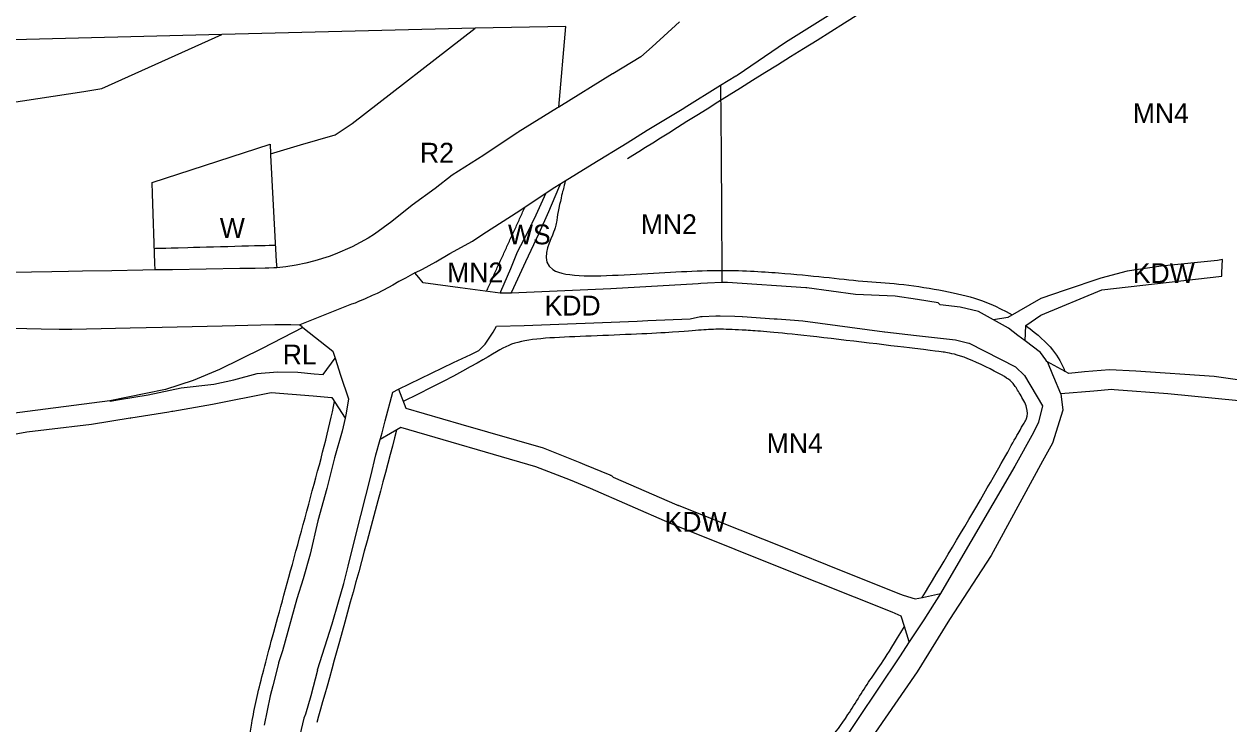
# Model space of a CAD drawing. Extents: x 7413438 to 7416393, y 5541665 to 5544118.
# Drawn here: x 7415261.6 to 7415625.7, y 5542999.4 to 5543211 of the extents above; entities that cross this region are included whole.
import ezdxf

# ---------------------------------------------------------------- set-up
doc = ezdxf.new("R2010")
doc.units = 0
for name, color, linetype in [('linie_rozgraniczajace', 7, 'Continuous'), ('linie_zabudowy_nieprzekraczalne', 7, 'Continuous'), ('oznaczenia_przeznaczen', 7, 'Continuous')]:
    doc.layers.add(name, color=color, linetype=linetype)

msp = doc.modelspace()

# ---------------------------------------------------------------- linework, layer by layer
at = {"layer": 'linie_rozgraniczajace'}
for p, q in [((7415491.71, 5543205.57), (7415509.39, 5543216.65)), ((7415397.9, 5543209.78), (7415321.33, 5543207.81)), ((7415360.73, 5543180.92), (7415397.9, 5543209.78)), ((7415425.26, 5543210.29), (7415397.9, 5543209.78)), ((7415423.19, 5543185.89), (7415425.26, 5543210.29)), ((7415459.66, 5543211.68), (7415451.33, 5543204.06)), ((7415321.33, 5543207.81), (7415254.41, 5543206.08)), ((7415285.02, 5543191.48), (7415321.33, 5543207.81)), ((7415477.03, 5543195.55), (7415491.71, 5543205.57)), ((7415451.33, 5543204.06), (7415447.97, 5543201.09)), ((7415447.97, 5543201.09), (7415439.5, 5543195.95)), ((7415439.43, 5543195.91), (7415423.19, 5543185.89)), ((7415439.5, 5543195.95), (7415439.43, 5543195.91)), ((7415472.07, 5543192.47), (7415476.65, 5543195.3)), ((7415476.65, 5543195.3), (7415476.73, 5543195.35)), ((7415476.73, 5543195.35), (7415477.03, 5543195.55)), ((7415256.5, 5543187.04), (7415279.6, 5543190.64)), ((7415279.6, 5543190.64), (7415285.02, 5543191.48)), ((7415461.04, 5543185.63), (7415472.07, 5543192.47)), ((7415472.07, 5543192.47), (7415472.21, 5543171.96)), ((7415422.79, 5543185.63), (7415410.86, 5543178.33)), ((7415423.19, 5543185.89), (7415422.79, 5543185.63)), ((7415449.91, 5543178.88), (7415460.96, 5543185.58)), ((7415460.96, 5543185.58), (7415461.04, 5543185.63)), ((7415355.58, 5543177.53), (7415360.73, 5543180.92)), ((7415345.11, 5543174.46), (7415355.58, 5543177.53)), ((7415410.54, 5543178.12), (7415400.48, 5543171.4)), ((7415410.74, 5543178.25), (7415410.54, 5543178.12)), ((7415410.86, 5543178.33), (7415410.74, 5543178.25)), ((7415443.8, 5543175.11), (7415449.91, 5543178.88)), ((7415300.24, 5543163.07), (7415335.89, 5543174.72)), ((7415335.89, 5543174.72), (7415336.05, 5543171.74)), ((7415336.05, 5543171.74), (7415345.11, 5543174.46)), ((7415433.28, 5543168.61), (7415443.8, 5543175.11)), ((7415336.05, 5543171.74), (7415336.07, 5543171.37)), ((7415336.07, 5543171.37), (7415337.79, 5543139.23)), ((7415400.48, 5543171.4), (7415390.95, 5543165.27)), ((7415472.21, 5543171.96), (7415472.33, 5543153.71)), ((7415390.95, 5543165.27), (7415385.76, 5543161.32)), ((7415423.77, 5543162.78), (7415433.25, 5543168.59)), ((7415433.25, 5543168.59), (7415433.28, 5543168.61)), ((7415300.35, 5543159.68), (7415300.24, 5543163.07)), ((7415421.48, 5543161.38), (7415423.77, 5543162.78)), ((7415423.15, 5543161.45), (7415423.77, 5543162.78)), ((7415301.08, 5543138.66), (7415300.35, 5543159.68)), ((7415385.76, 5543161.32), (7415378.88, 5543156.22)), ((7415411.51, 5543154.72), (7415419.23, 5543159.88)), ((7415419.23, 5543159.88), (7415416.2, 5543153.25)), ((7415419.23, 5543159.88), (7415421.48, 5543161.38)), ((7415420.15, 5543154.28), (7415423.15, 5543161.45)), ((7415378.88, 5543156.22), (7415372.72, 5543151.29)), ((7415400.25, 5543147.48), (7415411.36, 5543154.62)), ((7415411.36, 5543154.62), (7415411.51, 5543154.72)), ((7415417.24, 5543147.81), (7415420.15, 5543154.28)), ((7415372.72, 5543151.29), (7415367.43, 5543147.42)), ((7415416.2, 5543153.25), (7415413.74, 5543147.95)), ((7415472.33, 5543153.71), (7415472.45, 5543137)), ((7415367.43, 5543147.42), (7415365.51, 5543146.23)), ((7415397.08, 5543145.37), (7415400.25, 5543147.48)), ((7415413.74, 5543147.95), (7415410.62, 5543141.99)), ((7415413.21, 5543139.23), (7415417.24, 5543147.81)), ((7415360.69, 5543143.62), (7415355.56, 5543141.38)), ((7415365.51, 5543146.23), (7415360.69, 5543143.62)), ((7415390.25, 5543141.62), (7415397.08, 5543145.37)), ((7415353.72, 5543140.7), (7415349.44, 5543139.37)), ((7415355.56, 5543141.38), (7415353.72, 5543140.7)), ((7415386, 5543139.14), (7415390.25, 5543141.62)), ((7415410.62, 5543141.99), (7415408.59, 5543137.03)), ((7415623.74, 5543139.84), (7415622.21, 5543139.49)), ((7415623.56, 5543135.88), (7415623.74, 5543139.84)), ((7415270, 5543136.09), (7415257.64, 5543135.88)), ((7415274.96, 5543136.18), (7415270, 5543136.09)), ((7415279.27, 5543136.26), (7415274.96, 5543136.18)), ((7415288.11, 5543136.41), (7415279.27, 5543136.26)), ((7415297.42, 5543136.57), (7415288.11, 5543136.41)), ((7415301.15, 5543136.66), (7415297.42, 5543136.57)), ((7415301.15, 5543136.66), (7415301.08, 5543138.66)), ((7415306.39, 5543136.73), (7415301.15, 5543136.66)), ((7415326.8, 5543137.06), (7415306.39, 5543136.73)), ((7415331.38, 5543137.12), (7415326.8, 5543137.06)), ((7415334.46, 5543137.17), (7415331.38, 5543137.12)), ((7415335.54, 5543137.18), (7415334.46, 5543137.17)), ((7415337, 5543137.26), (7415335.54, 5543137.18)), ((7415337.92, 5543137.33), (7415337, 5543137.26)), ((7415337.79, 5543139.23), (7415337.92, 5543137.33)), ((7415340.64, 5543137.62), (7415337.92, 5543137.33)), ((7415343.84, 5543138.11), (7415340.64, 5543137.62)), ((7415346.73, 5543138.69), (7415343.84, 5543138.11)), ((7415349.44, 5543139.37), (7415346.73, 5543138.69)), ((7415379.69, 5543135.76), (7415381.97, 5543136.9)), ((7415381.97, 5543136.9), (7415386, 5543139.14)), ((7415408.59, 5543137.03), (7415405.53, 5543129.99)), ((7415409.56, 5543131.35), (7415413.21, 5543139.23)), ((7415472.45, 5543137), (7415472.47, 5543132.84)), ((7415594.94, 5543136.31), (7415586.97, 5543134.21)), ((7415605.22, 5543137.76), (7415594.94, 5543136.31)), ((7415622.21, 5543139.49), (7415605.22, 5543137.76)), ((7415374.79, 5543133.17), (7415372.96, 5543132.08)), ((7415376.83, 5543134.19), (7415374.79, 5543133.17)), ((7415379.68, 5543135.78), (7415376.83, 5543134.19)), ((7415379.69, 5543135.76), (7415379.68, 5543135.78)), ((7415380.87, 5543134.32), (7415379.69, 5543135.76)), ((7415382.16, 5543132.75), (7415380.87, 5543134.32)), ((7415393.33, 5543131.24), (7415382.16, 5543132.75)), ((7415465.24, 5543132.42), (7415438.88, 5543130.89)), ((7415466.1, 5543132.58), (7415465.24, 5543132.42)), ((7415468.14, 5543132.66), (7415466.1, 5543132.58)), ((7415472.47, 5543132.84), (7415468.14, 5543132.66)), ((7415473.58, 5543132.88), (7415472.47, 5543132.84)), ((7415473.91, 5543132.89), (7415473.58, 5543132.88)), ((7415474.13, 5543132.88), (7415473.91, 5543132.89)), ((7415497.78, 5543131.25), (7415474.13, 5543132.88)), ((7415586.97, 5543134.21), (7415576.2, 5543130.52)), ((7415587.27, 5543130.66), (7415623.51, 5543134.8)), ((7415623.51, 5543134.8), (7415623.56, 5543135.88)), ((7415366.78, 5543128.88), (7415364.64, 5543127.92)), ((7415368.23, 5543129.57), (7415366.78, 5543128.88)), ((7415369.97, 5543130.45), (7415368.23, 5543129.57)), ((7415371.68, 5543131.37), (7415369.97, 5543130.45)), ((7415372.96, 5543132.08), (7415371.68, 5543131.37)), ((7415405.41, 5543129.67), (7415393.33, 5543131.24)), ((7415405.39, 5543129.61), (7415405.41, 5543129.67)), ((7415408.74, 5543129.63), (7415405.39, 5543129.61)), ((7415405.53, 5543129.99), (7415405.41, 5543129.67)), ((7415408.76, 5543129.63), (7415408.74, 5543129.63)), ((7415408.79, 5543129.63), (7415408.76, 5543129.63)), ((7415438.88, 5543130.89), (7415408.79, 5543129.63)), ((7415408.79, 5543129.63), (7415408.8, 5543129.66)), ((7415408.8, 5543129.66), (7415409.56, 5543131.35)), ((7415497.89, 5543131.24), (7415497.78, 5543131.25)), ((7415498.11, 5543131.22), (7415497.89, 5543131.24)), ((7415512.8, 5543129.23), (7415498.11, 5543131.22)), ((7415524.86, 5543128.72), (7415512.8, 5543129.23)), ((7415531.51, 5543127.67), (7415524.86, 5543128.72)), ((7415576.2, 5543130.52), (7415568.79, 5543127.99)), ((7415568.85, 5543122.94), (7415587.27, 5543130.66)), ((7415360.53, 5543126.26), (7415344.85, 5543120.1)), ((7415361.58, 5543126.6), (7415360.53, 5543126.26)), ((7415362.84, 5543127.17), (7415361.58, 5543126.6)), ((7415362.93, 5543127.21), (7415362.84, 5543127.17)), ((7415364.64, 5543127.92), (7415362.93, 5543127.21)), ((7415537.84, 5543126.68), (7415531.51, 5543127.67)), ((7415538.45, 5543126.06), (7415537.84, 5543126.68)), ((7415544.48, 5543125.37), (7415538.45, 5543126.06)), ((7415550, 5543124.08), (7415544.48, 5543125.37)), ((7415568.79, 5543127.99), (7415558.88, 5543122.3)), ((7415450.1, 5543121.35), (7415462.82, 5543121.91)), ((7415462.82, 5543121.91), (7415466.02, 5543122.57)), ((7415466.02, 5543122.57), (7415466.53, 5543122.59)), ((7415466.53, 5543122.59), (7415470.65, 5543122.76)), ((7415470.65, 5543122.76), (7415471.86, 5543122.81)), ((7415471.86, 5543122.81), (7415471.89, 5543122.81)), ((7415471.89, 5543122.81), (7415471.89, 5543122.8)), ((7415471.89, 5543122.8), (7415476.32, 5543122.63)), ((7415476.32, 5543122.63), (7415478.55, 5543122.55)), ((7415478.55, 5543122.55), (7415478.58, 5543122.5)), ((7415478.58, 5543122.5), (7415478.65, 5543122.54)), ((7415478.65, 5543122.54), (7415488.28, 5543121.88)), ((7415488.28, 5543121.88), (7415489.11, 5543121.82)), ((7415489.11, 5543121.82), (7415493.04, 5543121.56)), ((7415493.04, 5543121.56), (7415496.93, 5543121.29)), ((7415554.55, 5543121.55), (7415550, 5543124.08)), ((7415558.88, 5543122.3), (7415554.55, 5543121.55)), ((7415559.05, 5543119.05), (7415554.55, 5543121.55)), ((7415564.25, 5543119.89), (7415568.85, 5543122.94)), ((7415253.51, 5543119.14), (7415266.71, 5543118.85)), ((7415266.71, 5543118.85), (7415272.17, 5543118.73)), ((7415272.17, 5543118.73), (7415276, 5543118.78)), ((7415276, 5543118.78), (7415280.43, 5543118.87)), ((7415280.43, 5543118.87), (7415293.6, 5543119.17)), ((7415293.6, 5543119.17), (7415303.33, 5543119.38)), ((7415303.33, 5543119.38), (7415321.44, 5543119.78)), ((7415321.44, 5543119.78), (7415333.16, 5543120.04)), ((7415333.16, 5543120.04), (7415337.35, 5543120.13)), ((7415345.8, 5543119.22), (7415333.55, 5543112.93)), ((7415337.35, 5543120.13), (7415342.17, 5543120.11)), ((7415342.17, 5543120.11), (7415344.88, 5543120.08)), ((7415344.85, 5543120.1), (7415344.88, 5543120.08)), ((7415344.88, 5543120.08), (7415345.58, 5543119.51)), ((7415345.58, 5543119.51), (7415345.43, 5543119.5)), ((7415345.43, 5543119.5), (7415345.8, 5543119.22)), ((7415345.8, 5543119.22), (7415354.88, 5543112.14)), ((7415400.88, 5543114.25), (7415403.28, 5543117.88)), ((7415403.28, 5543117.88), (7415404.33, 5543119.66)), ((7415404.33, 5543119.66), (7415412.66, 5543119.82)), ((7415412.66, 5543119.82), (7415446.83, 5543121.21)), ((7415446.83, 5543121.21), (7415450.1, 5543121.35)), ((7415496.93, 5543121.29), (7415521.62, 5543117.94)), ((7415521.62, 5543117.94), (7415521.72, 5543117.92)), ((7415521.72, 5543117.92), (7415531.27, 5543116.82)), ((7415561.92, 5543116.85), (7415559.05, 5543119.05)), ((7415564.05, 5543115.23), (7415564.25, 5543119.89)), ((7415399.02, 5543112.31), (7415400.88, 5543114.25)), ((7415531.27, 5543116.82), (7415543.03, 5543115.47)), ((7415543.03, 5543115.47), (7415547.1, 5543114.49)), ((7415547.1, 5543114.49), (7415547.14, 5543114.47)), ((7415547.14, 5543114.47), (7415561.21, 5543107.4)), ((7415564.05, 5543115.23), (7415561.92, 5543116.85)), ((7415568.7, 5543111.68), (7415564.05, 5543115.23)), ((7415333.55, 5543112.93), (7415320.59, 5543106.57)), ((7415354.88, 5543112.14), (7415355.58, 5543109.99)), ((7415391.3, 5543108.67), (7415396.6, 5543111.1)), ((7415396.6, 5543111.1), (7415399.02, 5543112.31)), ((7415570.31, 5543109.47), (7415568.7, 5543111.68)), ((7415351.94, 5543105.08), (7415355.58, 5543109.99)), ((7415355.58, 5543109.99), (7415357.22, 5543104.88)), ((7415374.75, 5543100.59), (7415391.3, 5543108.67)), ((7415561.21, 5543107.4), (7415563.86, 5543104.73)), ((7415570.66, 5543108.99), (7415570.31, 5543109.47)), ((7415570.9, 5543108.66), (7415570.66, 5543108.99)), ((7415577.25, 5543105.38), (7415570.66, 5543108.99)), ((7415572.41, 5543104.94), (7415570.9, 5543108.66)), ((7415312.67, 5543103.24), (7415304.33, 5543100.51)), ((7415320.59, 5543106.57), (7415312.67, 5543103.24)), ((7415318.88, 5543102.07), (7415324.94, 5543103.46)), ((7415324.94, 5543103.46), (7415332.05, 5543105.36)), ((7415332.05, 5543105.36), (7415338.18, 5543105.88)), ((7415338.18, 5543105.88), (7415344.34, 5543105.71)), ((7415344.34, 5543105.71), (7415349.25, 5543105.22)), ((7415349.25, 5543105.22), (7415351.94, 5543105.08)), ((7415357.22, 5543104.88), (7415359.56, 5543097.64)), ((7415563.86, 5543104.73), (7415569.31, 5543095.59)), ((7415572.71, 5543104.2), (7415572.41, 5543104.94)), ((7415574.9, 5543099.17), (7415572.71, 5543104.2)), ((7415582.03, 5543105.81), (7415577.25, 5543105.38)), ((7415587.03, 5543106.25), (7415582.03, 5543105.81)), ((7415589.54, 5543106.47), (7415587.03, 5543106.25)), ((7415597.51, 5543106.03), (7415589.54, 5543106.47)), ((7415621.18, 5543104.4), (7415597.51, 5543106.03)), ((7415629.01, 5543103.32), (7415621.18, 5543104.4)), ((7415304.33, 5543100.51), (7415298.4, 5543099.31)), ((7415299.03, 5543098.84), (7415309.05, 5543100.97)), ((7415309.05, 5543100.97), (7415318.88, 5543102.07)), ((7415318.46, 5543096.11), (7415336.27, 5543099.62)), ((7415336.27, 5543099.62), (7415348.92, 5543098.56)), ((7415370.64, 5543091.04), (7415373.03, 5543099.7)), ((7415373.03, 5543099.7), (7415374.75, 5543100.59)), ((7415374.75, 5543100.59), (7415376.9, 5543094.87)), ((7415584.83, 5543100.04), (7415574.9, 5543099.17)), ((7415590.26, 5543100.51), (7415584.83, 5543100.04)), ((7415591.01, 5543100.45), (7415590.26, 5543100.51)), ((7415607.16, 5543099.16), (7415591.01, 5543100.45)), ((7415287.51, 5543097.1), (7415257.2, 5543093.15)), ((7415298.4, 5543099.31), (7415287.51, 5543097.09)), ((7415287.51, 5543097.09), (7415287.51, 5543097.1)), ((7415287.51, 5543097.09), (7415287.55, 5543096.96)), ((7415287.55, 5543096.96), (7415290.41, 5543097.43)), ((7415290.41, 5543097.43), (7415299.03, 5543098.84)), ((7415306.49, 5543093.97), (7415318.46, 5543096.11)), ((7415348.92, 5543098.56), (7415354.51, 5543098.09)), ((7415354.51, 5543098.09), (7415354.51, 5543098.1)), ((7415354.51, 5543098.1), (7415354.57, 5543098.09)), ((7415354.57, 5543098.09), (7415358.6, 5543091.88)), ((7415359.56, 5543097.64), (7415358.91, 5543093.34)), ((7415574.9, 5543099.17), (7415575.46, 5543094.21)), ((7415628.64, 5543097.08), (7415607.16, 5543099.16)), ((7415293.87, 5543091.93), (7415305.29, 5543093.75)), ((7415305.29, 5543093.75), (7415306.2, 5543094)), ((7415306.2, 5543094), (7415306.49, 5543093.97)), ((7415358.91, 5543093.34), (7415358.6, 5543091.88)), ((7415376.9, 5543094.87), (7415393.53, 5543090.01)), ((7415569.31, 5543095.59), (7415568.13, 5543090.63)), ((7415575.46, 5543094.21), (7415572.36, 5543084.32)), ((7415268.36, 5543088.38), (7415281.92, 5543089.99)), ((7415281.92, 5543089.99), (7415293.58, 5543091.89)), ((7415293.58, 5543091.89), (7415293.81, 5543091.83)), ((7415293.81, 5543091.83), (7415293.87, 5543091.93)), ((7415358.6, 5543091.88), (7415357.73, 5543087.87)), ((7415375.38, 5543088.99), (7415369.19, 5543085.36)), ((7415369.76, 5543087.37), (7415370.64, 5543091.04)), ((7415416.21, 5543077.12), (7415375.38, 5543088.99)), ((7415393.53, 5543090.01), (7415418.46, 5543082.89)), ((7415568.13, 5543090.63), (7415566.58, 5543087.47)), ((7415256.96, 5543086.68), (7415262.38, 5543087.69)), ((7415262.38, 5543087.69), (7415268.36, 5543088.38)), ((7415357.73, 5543087.87), (7415355.35, 5543079.88)), ((7415367.89, 5543080.72), (7415369.19, 5543085.36)), ((7415369.19, 5543085.36), (7415369.76, 5543087.37)), ((7415566.58, 5543087.47), (7415560.99, 5543077.3)), ((7415418.46, 5543082.89), (7415429.51, 5543078.39)), ((7415572.36, 5543084.32), (7415569.37, 5543078.83)), ((7415355.35, 5543079.88), (7415353.01, 5543070.58)), ((7415366.34, 5543074.33), (7415367.89, 5543080.72)), ((7415429.51, 5543078.39), (7415430.91, 5543077.81)), ((7415430.91, 5543077.81), (7415438.59, 5543074.68)), ((7415569.37, 5543078.83), (7415556.24, 5543054.72)), ((7415363.37, 5543062.45), (7415366.34, 5543074.33)), ((7415426.68, 5543073.06), (7415416.21, 5543077.12)), ((7415438.59, 5543074.68), (7415438.68, 5543074.64)), ((7415438.68, 5543074.64), (7415438.85, 5543074.56)), ((7415438.85, 5543074.56), (7415439.02, 5543074.46)), ((7415439.02, 5543074.46), (7415439.19, 5543074.35)), ((7415439.19, 5543074.35), (7415439.34, 5543074.24)), ((7415439.34, 5543074.24), (7415439.49, 5543074.11)), ((7415439.49, 5543074.11), (7415439.6, 5543074.01)), ((7415560.99, 5543077.3), (7415540.98, 5543043.12)), ((7415353.01, 5543070.58), (7415350.37, 5543060.77)), ((7415432.71, 5543070.6), (7415426.68, 5543073.06)), ((7415456.67, 5543060.13), (7415432.71, 5543070.6)), ((7415439.6, 5543074.01), (7415458.81, 5543065.59)), ((7415458.81, 5543065.59), (7415459, 5543065.55)), ((7415459, 5543065.55), (7415459.19, 5543065.5)), ((7415459.19, 5543065.5), (7415459.37, 5543065.44)), ((7415459.37, 5543065.44), (7415459.45, 5543065.41)), ((7415459.45, 5543065.41), (7415460.79, 5543064.88)), ((7415460.79, 5543064.88), (7415471.53, 5543060.58)), ((7415350.37, 5543060.77), (7415347.98, 5543050.73)), ((7415361.37, 5543054.89), (7415363.37, 5543062.45)), ((7415456.78, 5543060.06), (7415456.67, 5543060.13)), ((7415456.95, 5543059.97), (7415456.78, 5543060.06)), ((7415457.12, 5543059.88), (7415456.95, 5543059.97)), ((7415457.23, 5543059.84), (7415457.12, 5543059.88)), ((7415458.65, 5543059.27), (7415457.23, 5543059.84)), ((7415471.53, 5543060.58), (7415491.03, 5543052.78)), ((7415476.47, 5543052.14), (7415458.65, 5543059.27)), ((7415359.55, 5543047.09), (7415361.37, 5543054.89)), ((7415491.03, 5543052.78), (7415508.54, 5543045.78)), ((7415556.24, 5543054.72), (7415553.85, 5543050.33)), ((7415347.98, 5543050.73), (7415345.9, 5543043.25)), ((7415489.77, 5543046.82), (7415476.47, 5543052.14)), ((7415553.85, 5543050.33), (7415541.24, 5543030.91)), ((7415358.2, 5543041.86), (7415359.55, 5543047.09)), ((7415523.93, 5543033.16), (7415489.77, 5543046.82)), ((7415508.54, 5543045.78), (7415526.46, 5543038.61)), ((7415345.9, 5543043.25), (7415344.01, 5543037.17)), ((7415356.62, 5543036.29), (7415358.2, 5543041.86)), ((7415540.98, 5543043.12), (7415538.46, 5543038.82)), ((7415526.46, 5543038.61), (7415527.19, 5543038.32)), ((7415527.19, 5543038.32), (7415530.88, 5543037.16)), ((7415533.02, 5543037.63), (7415538.46, 5543038.82)), ((7415538.46, 5543038.82), (7415533.51, 5543030.82)), ((7415344.01, 5543037.17), (7415339.63, 5543021.46)), ((7415354.67, 5543029.63), (7415356.62, 5543036.29)), ((7415530.88, 5543037.16), (7415533.02, 5543037.63)), ((7415526.64, 5543032.01), (7415523.93, 5543033.16)), ((7415527.61, 5543028.88), (7415526.64, 5543032.01)), ((7415533.51, 5543030.82), (7415529.08, 5543024.18)), ((7415541.24, 5543030.91), (7415531.45, 5543015.17)), ((7415350.24, 5543015.76), (7415354.67, 5543029.63)), ((7415529.08, 5543024.18), (7415527.61, 5543028.88)), ((7415529.08, 5543024.18), (7415526.08, 5543019.69)), ((7415339.63, 5543021.46), (7415338.47, 5543017.81)), ((7415526.08, 5543019.69), (7415495.03, 5542973.19)), ((7415338.47, 5543017.67), (7415336.7, 5543010.88)), ((7415338.47, 5543017.81), (7415338.47, 5543017.67)), ((7415348.35, 5543007.96), (7415350.3, 5543015.74)), ((7415350.29, 5543015.74), (7415350.24, 5543015.76)), ((7415350.3, 5543015.74), (7415350.29, 5543015.74)), ((7415531.45, 5543015.17), (7415515.94, 5542992.61)), ((7415336.7, 5543010.88), (7415335.89, 5543007.91)), ((7415335.89, 5543007.91), (7415334.12, 5542998.99)), ((7415346.74, 5543002.43), (7415348.35, 5543007.96)), ((7415346.24, 5543001.19), (7415346.74, 5543002.43)), ((7415345.05, 5542996.02), (7415346.21, 5543001.13)), ((7415346.21, 5543001.13), (7415346.24, 5543001.19)), ((7415346.21, 5543001.13), (7415346.21, 5543001.13))]:
    msp.add_line(p, q, dxfattribs=at)
at = {"layer": 'linie_zabudowy_nieprzekraczalne'}
for points, degree in [([(7415657.6, 5543302.19), (7415645.23, 5543296.35), (7415476.29, 5543190.53), (7415443.93, 5543170.24)], 3), ([(7415425.11, 5543163.6), (7415424.64, 5543161.39), (7415424.3, 5543160.76), (7415422.07, 5543149.96), (7415422.54, 5543149.85), (7415415.09, 5543133.84), (7415445.21, 5543135.25), (7415472.43, 5543136.99), (7415490.3, 5543135.76), (7415503.53, 5543134.51), (7415515.34, 5543133.11), (7415525.47, 5543132.66), (7415538.45, 5543130.62), (7415549.05, 5543128.39), (7415554.9, 5543125.91), (7415560.2, 5543123.05)], 3), ([(7415401.3, 5543130.19), (7415412.96, 5543155.68)], 1), ([(7415300.9, 5543143.18), (7415300.95, 5543143.18), (7415302.34, 5543143.22), (7415302.35, 5543143.22), (7415337.06, 5543144.16), (7415337.52, 5543144.18)], 3), ([(7415533.01, 5543037.61), (7415537.93, 5543045.82), (7415554.23, 5543072.99), (7415563.18, 5543089.67), (7415564.7, 5543091.43), (7415565.03, 5543094.93), (7415562.44, 5543099.28), (7415560.67, 5543102.25), (7415558.83, 5543104.1), (7415545.71, 5543110.69), (7415539.2, 5543111.87), (7415538.43, 5543111.95), (7415491.43, 5543117.64), (7415478.88, 5543118.5), (7415471.85, 5543118.79), (7415466.49, 5543118.57), (7415459.31, 5543117.74), (7415427.96, 5543116.43), (7415406.6, 5543115.65), (7415401.57, 5543109.22), (7415376.12, 5543096.91)], 3), ([(7415564.24, 5543119.88), (7415571.76, 5543114.23), (7415574.4, 5543110.56), (7415576.08, 5543105.99)], 3), ([(7415224.24, 5542764.93), (7415234.87, 5542768.93), (7415252.45, 5542775.15), (7415267.62, 5542778.59), (7415300.4, 5542786.16), (7415306.31, 5542787.89), (7415321.64, 5542794.04), (7415341.99, 5542803.09), (7415373.83, 5542816.66), (7415358.63, 5542848.96), (7415349.07, 5542869.68), (7415324.44, 5542923.07), (7415321.98, 5542928.69), (7415321.86, 5542932.66), (7415323.07, 5542937.93), (7415326.67, 5542952.06), (7415325.97, 5542960.66), (7415326.79, 5542972.64), (7415328.33, 5542984.95), (7415330.18, 5542999.75), (7415333.24, 5543013.48), (7415339.07, 5543034.4), (7415348.26, 5543068.35), (7415353.84, 5543088.85), (7415355.35, 5543096.84)], 3), ([(7415374.11, 5543088.24), (7415367.74, 5543063.5), (7415355.79, 5543020.01), (7415350.02, 5542999.79)], 3), ([(7415398.75, 5542825.57), (7415425.57, 5542832.86), (7415430.65, 5542835.5), (7415456.62, 5542854.66), (7415458.62, 5542861.54), (7415457.28, 5542881.79), (7415456.66, 5542890.14), (7415456.81, 5542901), (7415458.48, 5542906.91), (7415468.57, 5542933.52), (7415473.53, 5542946.04), (7415483.62, 5542964.23), (7415502.34, 5542990.63), (7415505, 5542994.59), (7415510.05, 5543001.09), (7415518.09, 5543014.38), (7415521.57, 5543018.72), (7415527.6, 5543028.87)], 3)]:
    msp.add_open_spline(points, degree=degree, dxfattribs=at)

# ---------------------------------------------------------------- texts
at = {"layer": 'oznaczenia_przeznaczen'}
for s, p in [('MN4', (7415596.63, 5543181.03)), ('R2', (7415381.21, 5543169.09)), ('W', (7415320.72, 5543146.34)), ('MN2', (7415447.94, 5543147.47)), ('WS', (7415407.79, 5543144.39)), ('MN2', (7415389.41, 5543132.89)), ('KDW', (7415596.63, 5543132.69)), ('KDD', (7415418.87, 5543122.87)), ('RL', (7415339.73, 5543108.07)), ('MN4', (7415485.99, 5543081.28)), ('KDW', (7415455.14, 5543057.48))]:
    msp.add_text(s, height=6, dxfattribs=at).set_placement(p)

doc.saveas('drawing.dxf')
